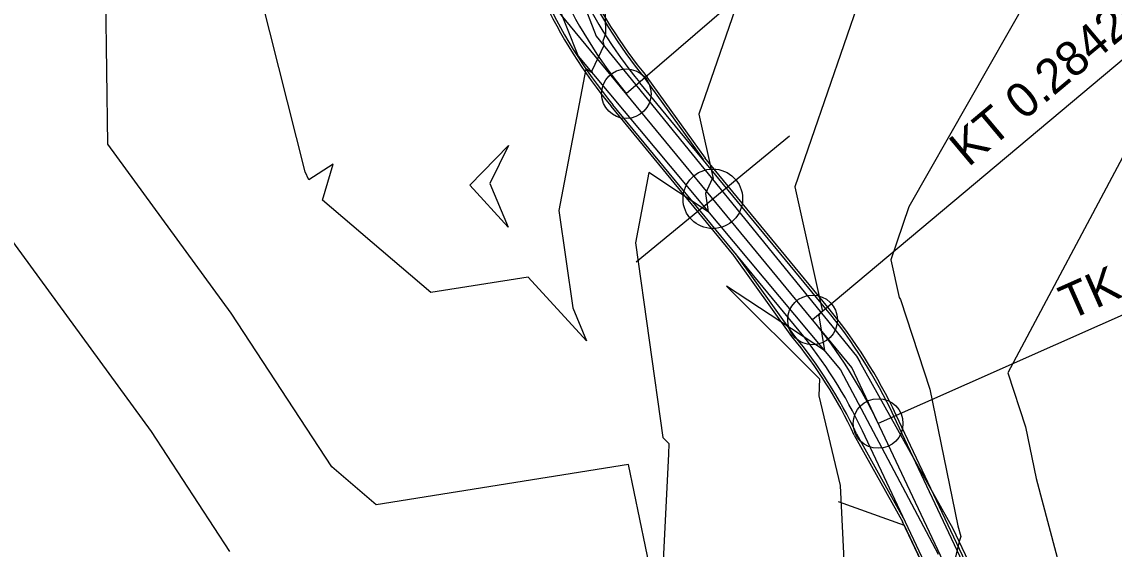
# Model space of a CAD drawing. Extents: x -549394 to -546608, y -1037055 to -1033629.
# Drawn here: x -547917.4 to -547807.4, y -1034715 to -1034661.9 of the extents above; entities that cross this region are included whole.
import ezdxf

# ---------------------------------------------------------------- set-up
doc = ezdxf.new("R2010")
doc.units = 0
for name, color, linetype in [('03_PC_OBJEKTY_STAV', 7, 'Continuous'), ('hlavni_vrst', 7, 'Continuous'), ('hrana_L', 7, 'Continuous'), ('norm_vrst', 7, 'Continuous'), ('POLYGONY_SITUACE_PO', 7, 'Continuous'), ('u_sirka_1_0m', 7, 'Continuous'), ('x_navrh_C21', 7, 'Continuous'), ('x_osa_C21', 7, 'Continuous'), ('x_popis_oblouky_C21', 7, 'Continuous'), ('x_popis_pricne_rezy_C21', 7, 'Continuous'), ('x_popis_velky_C21', 7, 'Continuous')]:
    doc.layers.add(name, color=color, linetype=linetype)

msp = doc.modelspace()

# ---------------------------------------------------------------- linework, layer by layer
at = {"layer": '03_PC_OBJEKTY_STAV'}
msp.add_lwpolyline([(-547835.16, -1034710.23), (-547828.5, -1034712.62), (-547824.24, -1034721.67), (-547826.63, -1034728.32)], dxfattribs=at)
at = {"layer": 'hlavni_vrst'}
for p, q in [((-547813.16, -1034654.45), (-547828.03, -1034680.56)), ((-547828.03, -1034680.56), (-547829.86, -1034685.88)), ((-547829.86, -1034685.88), (-547829.02, -1034689.67)), ((-547829.02, -1034689.67), (-547828.86, -1034689.87)), ((-547828.86, -1034689.87), (-547825.93, -1034698.92)), ((-547825.93, -1034698.92), (-547823.08, -1034712.7)), ((-547823.08, -1034712.7), (-547822.79, -1034713.78)), ((-547822.95, -1034714.28), (-547823.74, -1034717.53)), ((-547822.79, -1034713.78), (-547822.95, -1034714.28))]:
    msp.add_line(p, q, dxfattribs=at)
at = {"layer": 'hrana_L'}
for p, q in [((-547865.04, -1034649.22), (-547859.51, -1034663.34)), ((-547867.33, -1034650.32), (-547861.32, -1034665.38)), ((-547859.51, -1034663.34), (-547833.31, -1034695.61)), ((-547861.32, -1034665.38), (-547834.9, -1034696.97)), ((-547833.31, -1034695.61), (-547832.97, -1034696.15)), ((-547823.55, -1034712.99), (-547832.97, -1034696.15)), ((-547834.9, -1034696.97), (-547825.09, -1034715.55)), ((-547816.3, -1034728.43), (-547823.55, -1034712.99))]:
    msp.add_line(p, q, dxfattribs=at)
at = {"layer": 'norm_vrst'}
for p, q in [((-547888.82, -1034677.02), (-547902.54, -1034622.79)), ((-547908.68, -1034674.25), (-547909.16, -1034640.94)), ((-547858.84, -1034650.41), (-547858.58, -1034663.11)), ((-547831.89, -1034656.41), (-547839.52, -1034678.54)), ((-547845.23, -1034659.76), (-547849.18, -1034671.2)), ((-547858.58, -1034663.11), (-547858.83, -1034663.85)), ((-547858.83, -1034663.85), (-547858.74, -1034664.28)), ((-547858.75, -1034664.28), (-547859.95, -1034666.86)), ((-547858.74, -1034664.28), (-547858.75, -1034664.28)), ((-547860.56, -1034666.63), (-547863.27, -1034680.92)), ((-547859.92, -1034667.06), (-547860.56, -1034666.63)), ((-547859.95, -1034666.86), (-547859.92, -1034667.06)), ((-547904.3, -1034703.2), (-547929.91, -1034668.08)), ((-547849.18, -1034671.2), (-547847.72, -1034677.69)), ((-547896.27, -1034691.27), (-547908.68, -1034674.25)), ((-547872.25, -1034678.35), (-547868.33, -1034674.37)), ((-547868.33, -1034674.37), (-547870.21, -1034678.21)), ((-547805.95, -1034674.5), (-547818.05, -1034697.26)), ((-547888.45, -1034677.82), (-547888.82, -1034677.02)), ((-547886, -1034676.25), (-547888.45, -1034677.82)), ((-547887.09, -1034679.88), (-547886, -1034676.25)), ((-547854.23, -1034677.09), (-547855.57, -1034684.16)), ((-547848.23, -1034681.04), (-547854.23, -1034677.09)), ((-547870.21, -1034678.21), (-547868.37, -1034682.6)), ((-547847.83, -1034677.73), (-547848.52, -1034679.2)), ((-547847.72, -1034677.69), (-547847.83, -1034677.73)), ((-547868.37, -1034682.6), (-547872.25, -1034678.35)), ((-547848.52, -1034679.2), (-547848.23, -1034681.04)), ((-547839.52, -1034678.54), (-547836.71, -1034691.1)), ((-547876.18, -1034689.17), (-547887.09, -1034679.88)), ((-547863.27, -1034680.92), (-547861.88, -1034690.74)), ((-547855.57, -1034684.16), (-547852.81, -1034703.78)), ((-547866.37, -1034687.62), (-547876.18, -1034689.17)), ((-547860.5, -1034694.04), (-547866.37, -1034687.62)), ((-547836.54, -1034695.01), (-547846.39, -1034688.54)), ((-547846.39, -1034688.54), (-547837.02, -1034697.88)), ((-547886.13, -1034706.76), (-547896.27, -1034691.27)), ((-547861.88, -1034690.74), (-547860.5, -1034694.04)), ((-547836.91, -1034691.17), (-547837.08, -1034691.54)), ((-547836.71, -1034691.1), (-547836.91, -1034691.17)), ((-547837.08, -1034691.54), (-547836.54, -1034695.01)), ((-547837.02, -1034697.88), (-547837.09, -1034699.6)), ((-547818.05, -1034697.26), (-547816.29, -1034702.71)), ((-547837.09, -1034699.6), (-547834.94, -1034708.62)), ((-547896.4, -1034715.27), (-547904.3, -1034703.2)), ((-547816.29, -1034702.71), (-547815.21, -1034707.93)), ((-547852.81, -1034703.78), (-547852.19, -1034704.4)), ((-547852.19, -1034704.4), (-547852.23, -1034705.46)), ((-547852.23, -1034705.46), (-547852.92, -1034718.94)), ((-547881.67, -1034710.56), (-547886.13, -1034706.76)), ((-547856.25, -1034706.52), (-547881.67, -1034710.56)), ((-547853.65, -1034719.19), (-547856.25, -1034706.52)), ((-547834.94, -1034708.62), (-547834.94, -1034708.62)), ((-547834.94, -1034708.62), (-547834.94, -1034708.62)), ((-547834.94, -1034708.62), (-547834.94, -1034708.62)), ((-547834.94, -1034708.62), (-547834.18, -1034724.62)), ((-547815.21, -1034707.93), (-547810.13, -1034727.01))]:
    msp.add_line(p, q, dxfattribs=at)
at = {"layer": 'POLYGONY_SITUACE_PO'}
for centre in [(-547856.48, -1034669.15), (-547837.73, -1034691.94), (-547831.12, -1034702.38)]:
    msp.add_circle(centre, 2.5, dxfattribs=at)
at = {"layer": 'u_sirka_1_0m'}
msp.add_circle((-547847.77, -1034679.74), 3, dxfattribs=at)
at = {"layer": 'x_navrh_C21'}
for p, q in [((-547854.6, -1034667.63), (-547848.75, -1034675.79)), ((-547854.4, -1034667.47), (-547848.55, -1034675.64)), ((-547845.63, -1034685.48), (-547858.02, -1034670.42)), ((-547836.19, -1034690.66), (-547848.57, -1034675.61)), ((-547839.81, -1034693.61), (-547845.65, -1034685.45)), ((-547839.61, -1034693.46), (-547845.46, -1034685.3)), ((-547820.98, -1034719.18), (-547829.31, -1034701.53)), ((-547833.3, -1034703.43), (-547828.42, -1034712.2)), ((-547833.52, -1034703.54), (-547828.64, -1034712.31)), ((-547820.33, -1034729.95), (-547828.66, -1034712.28))]:
    msp.add_line(p, q, dxfattribs=at)
for centre, radius, start, end in [((-547817.86, -1034637.38), 47.58, 189.1036, 219.4646), ((-547817.86, -1034637.38), 47.33, 189.0918, 219.4748), ((-547817.86, -1034637.38), 52, 190.6794, 219.4445), ((-547876.34, -1034723.7), 52, 25.2434, 39.4445), ((-547876.34, -1034723.7), 47.58, 25.2233, 39.4646), ((-547876.34, -1034723.7), 47.33, 25.2131, 39.4748)]:
    msp.add_arc(centre, radius, start, end, dxfattribs=at)
at = {"layer": 'x_osa_C21'}
msp.add_lwpolyline([(-547815.62, -1034735.25), (-547833.77, -1034696.75), (-547865.08, -1034658.69)], dxfattribs=at)
for centre, start, end in [((-547817.86, -1034637.38), 189.1269, 219.4445), ((-547876.34, -1034723.7), 25.2434, 39.4445)]:
    msp.add_arc(centre, 50, start, end, dxfattribs=at)
at = {"layer": 'x_popis_oblouky_C21'}
for points in [[(-547830.6, -1034646.85), (-547856.48, -1034669.15)], [(-547804.05, -1034663.69), (-547837.73, -1034691.94)], [(-547790.95, -1034684.53), (-547831.12, -1034702.38)]]:
    msp.add_lwpolyline(points, dxfattribs=at)
at = {"layer": 'x_popis_pricne_rezy_C21'}
msp.add_lwpolyline([(-547855.49, -1034686.09), (-547847.77, -1034679.74), (-547840.05, -1034673.38)], dxfattribs=at)
at = {"layer": 'x_popis_velky_C21'}
for p, q in [((-547836.38, -1034690.82), (-547855.12, -1034668.04)), ((-547839.08, -1034693.05), (-547857.83, -1034670.26)), ((-547816.94, -1034728.35), (-547829.53, -1034701.63)), ((-547820.1, -1034729.84), (-547832.7, -1034703.12))]:
    msp.add_line(p, q, dxfattribs=at)
for centre, radius, start, end in [((-547817.86, -1034637.38), 48.25, 189.1269, 219.4445), ((-547817.86, -1034637.38), 51.75, 189.1269, 219.4445), ((-547876.34, -1034723.7), 51.75, 25.2434, 39.4445), ((-547876.34, -1034723.7), 48.25, 25.2434, 39.4445)]:
    msp.add_arc(centre, radius, start, end, dxfattribs=at)

# ---------------------------------------------------------------- texts
at = {"layer": 'x_popis_oblouky_C21'}
for s, rotation, p in [('KT 0.28420', 39.9916, (-547822.04, -1034676.61)), ('TK 0.27181', 23.9597, (-547811.84, -1034692))]:
    msp.add_text(s, height=3.5, rotation=rotation, dxfattribs=at).set_placement(p)

doc.saveas('drawing.dxf')
